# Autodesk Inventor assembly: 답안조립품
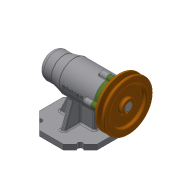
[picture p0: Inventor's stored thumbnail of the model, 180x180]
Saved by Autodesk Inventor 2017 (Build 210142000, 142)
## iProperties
Created: 2019-12
Part Number: 답안조립품
Document SubType Name: Assembly
Designer: 5-10-le
Author: 5-10-le
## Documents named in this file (12)
- C:\Users\5-10-le\Desktop\491204V1010\답안조립품.iam
- C:\Users\5-10-le\Desktop\491204V1010\본체.ipt
- C:\Users\5-10-le\Desktop\491204V1010\오일 실.ipt
- C:\Users\5-10-le\Desktop\491204V1010\축.ipt
- C:\Users\5-10-le\Desktop\491204V1010\커버.ipt
- C:\Users\5-10-le\Desktop\491204V1010\키 5 x 5 x 16.ipt
- C:\Users\5-10-le\Desktop\491204V1010\볼트 M4.ipt
- C:\Users\5-10-le\Desktop\491204V1010\어댑터슬리브.ipt
- C:\Users\5-10-le\Desktop\491204V1010\멈춤나사 M3.ipt
- C:\Users\5-10-le\Desktop\491204V1010\베어링 6004.ipt
- C:\Users\5-10-le\Desktop\491204V1010\베어링 51202.ipt
- C:\Users\5-10-le\Desktop\491204V1010\V벨트풀리.ipt
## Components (1 placed, 1 different names)
1. V벨트풀리:1
